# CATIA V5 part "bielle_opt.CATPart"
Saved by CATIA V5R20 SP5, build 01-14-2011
Part number: Part1
Bounding box of the stored display mesh (mm): x 0 to 5, y -7.954 to 67.954, z -7.994 to 7.994
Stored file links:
  U:\IAO\bielle_opt.CATPart
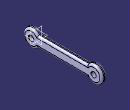
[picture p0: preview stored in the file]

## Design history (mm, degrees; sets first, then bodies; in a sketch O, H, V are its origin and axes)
Body1 (main body)
  Sketch1 on yz-plane, origin (0, 0, 0), H (0, 1, 0), V (0, 0, 1)
    circle A1 centre (0, 0) radius 2.5
    circle A2 centre (60, 0) radius 2.5
    point P1 (60, 0)
    construction line L1 (0, 0) -> (60, 0)
    construction line L2 (0, 0) -> (60, 0)
    line L3 (6.245, 5) -> (53.755, 5)
    line L4 (53.755, -5) -> (6.245, -5)
    arc A3 centre (60, 0) radius 8 from (53.755, 5) to (53.755, -5) cw
    arc A4 centre (0, 0) radius 8 from (6.245, -5) to (6.245, 5) cw
    radius A1 = 2.5
    radius A2 = 2.5
    distance P1 O = 60
    distance L2 L3 = 5
    distance L4 L2 = 5
    radius A3 = 8
    radius A4 = 8
    horizontal: L1 H, L2 H
  Pad1: profile Sketch1, direction (1, 0, 0), length 5
  Fillet1: radius 2, on edge [start face of Pad1 | face of Pad1 from Sketch1.L4]; edge [face of Pad1 from Sketch1.L4 | end face of Pad1]; edge [start face of Pad1 | face of Pad1 from Sketch1.L3]; edge [face of Pad1 from Sketch1.L3 | end face of Pad1]
  Fillet2: radius 2, on edge [start face of Pad1 | face of Pad1 from Sketch1.A4]; edge [face of Pad1 from Sketch1.A4 | end face of Pad1]; edge [face of Pad1 from Sketch1.A3 | end face of Pad1]; edge [start face of Pad1 | face of Pad1 from Sketch1.A3]
  Sketch2 on start face of Pad1, origin (0, 0, 0), H (0, -1, 0), V (0, 0, 1)
  Sketch3 on end face of Pad1, origin (5, 0, 0), H (0, 1, 0), V (0, 0, 1)
    line L1 (52.5838, 3) -> (7, 3)
    line L2 (52.5838, -3) -> (7, -3)
    point P4 (7, -3)
    arc A1 centre (60, 0) radius 8 from (52.5838, 3) to (52.5838, -3) ccw
    point P6 (52, 0)
    arc A2 centre (0, 0) radius 7.6158 from (7, 3) to (7, -3) cw
    point P8 (7.6158, 0)
    point P9 (7, -3)
    horizontal: L1 H, L2 H
    coincidence: A1 P6, P6 H, A2 P8, P8 H, P9 L2, A2 P4, P4 P9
